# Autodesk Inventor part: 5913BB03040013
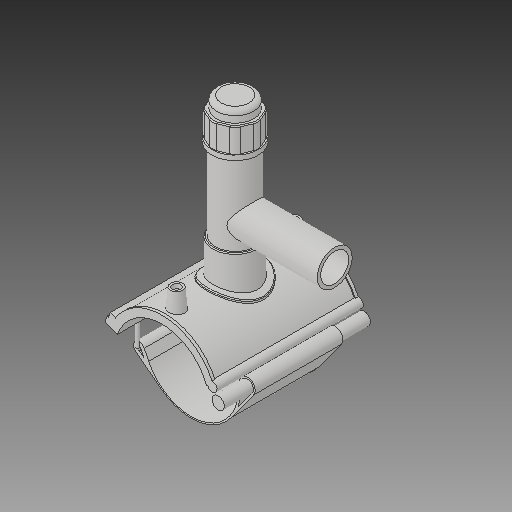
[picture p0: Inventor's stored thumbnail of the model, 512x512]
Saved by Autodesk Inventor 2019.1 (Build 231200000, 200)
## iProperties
Created: 2017-07
Part Number: 5913BB03040013
Material: Generic
Description: PLASSON TAPPING SADDLE 4''IPS x 1 1/4''IPS
Document SubType Name: Modeling
Designer: KIM
Mass: 1712.7 g
Surface Area: 2671.49 cm^2
Volume: 1712.7 cm^3
Density: 1 g/cm^3
Appearance: Default
Author: KIM
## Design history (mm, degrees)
derived "5913B.ipt"
feature "Solid1::5913B.ipt"
feature "Solid2::5913B.ipt"
feature "Solid4::5913B.ipt"
feature "Solid5::5913B.ipt"
tag "TaggingFeature1"
body "Solid1"
body "Solid2"
other parameters: "d0" = 114.1, "d2" = 233.934, "d3" = 28.525, "d4" = 176.022, "d5" = 0, "d6" = 0.1, "d8" = 0, "d40" = 67.63848, "d41" = 68.46, "d43" = 0, "d45" = 0, "d47" = 170.6502, "d78" = 87.05, "d79" = 15, "d80" = 70.4088, "d82" = 5 deg, "d84" = 4, "d85" = 14, "d86" = 0, "d87" = 3, "d88" = 0, "d96" = 132.67548, "d97" = 3.52044, "d98" = 0, "d102" = 1.141, "d120" = 140 deg, "d121" = 24.228, "d122" = 20 deg, "d123" = 325.185, "d124" = 78.0444, "d126" = 0, "d153" = 176.022, "d154" = 0, "d159" = 3.1948, "d162" = 105.6132, "d163" = 0, "d164" = 57.05, "d169" = 4.0905, "d170" = 4.7922, "d172" = 0, "d173" = 1, "d175" = 57.05, "d176" = 20 deg, "d177" = 7.987, "d178" = 15.974, "d180" = 0, "d183" = 6.3896, "d184" = 6.3896, "d187" = 65.037, "d188" = 4.7922, "d189" = 7.987, "d190" = 0, "d191" = 97.5555, "d193" = 4.1076, "d194" = 2.0538, "d195" = 90 deg, "d197" = 0, "d199" = 0, "d200" = 7.987, "d202" = 0, "d203" = 194.818, "d204" = 53.33034, "d205" = 39.29604, "d206" = 47.71662, "d207" = 146.1135, "d208" = 151.95804, "d209" = 181.18074, "d210" = 48.27799, "d211" = 56.1372, "d212" = 44.90976, "d213" = 48.492, "d216" = 0, "d217" = 11.41, "d218" = 5.705, "d219" = 1.141, "d222" = 114.1, "d224" = 0, "d230" = 1.141, "d257" = 131.98, "d258" = 119.888, "d259" = 33.68, "d260" = 42.1, "d263" = 155.956, "d265" = 0, "d267" = 13.00006, "d268" = 2.60001, "d269" = 2.60001, "d271" = 2.60001, "d273" = 0, "d274" = 23.56194, "d275" = 91.28, "d277" = 45.64, "d278" = 182.56, "d280" = 0, "d281" = 114.1, "d283" = 0, "d285" = 0, "d290" = 11.41, "d291" = 14.833, "d293" = 62.755, "d294" = 58.7615, "d296" = 17.115, "d297" = 13.692, "d_" = 114.1, "B_" = 155.956, "L_" = 176.022, "d_t" = 6, "H_2" = 194.818, "H_1" = 74.93, "d_1" = 42.1, "H_" = 119.888, "d1" = 130.074, "d192" = 4.1076
